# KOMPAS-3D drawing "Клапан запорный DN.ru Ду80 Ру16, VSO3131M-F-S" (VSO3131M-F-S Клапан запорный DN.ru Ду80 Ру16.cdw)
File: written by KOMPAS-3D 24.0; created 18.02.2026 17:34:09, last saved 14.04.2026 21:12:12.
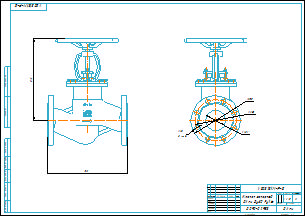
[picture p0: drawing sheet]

Document properties: Автор: R2D2; Форматы листов документа: A2; Полное имя файла: VSO3131M-F-S Клапан запорный DN.ru Ду80 Ру16.m3d; Масса: 20.25; Наименование: Клапан запорный DN.ru Ду80 Ру16; Количество листов документа: 1; Примечание: D090-02953

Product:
- Part/product: Клапан запорный DN.ru Ду80 Ру16  | designation VSO3131M-F-S
    Масса: 20.25
    Раздел спецификации: Прочие изделия
    Примечание: D090-02953

Views: Вид 1, Спереди, Проекционный вид 2
Referenced files in E:\Работа\Зайцев\VSO3131M-F-S Клапан запорный DN.ru Ду15-100 Ру40\DN50\: VSO3131M-F-S Клапан запорный DN.ru Ду50 Ру40.m3d
Referenced files in E:\Работа\Зайцев\VSO3131M-F-S Клапан запорный DN.ru Ду15-100 Ру16\DN80\: VSO3131M-F-S Клапан запорный DN.ru Ду80 Ру16.m3d
Referenced files in E:\Работа\Зайцев\Для компаса\: чертеж DN.ru А3.cdt
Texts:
  Линейный размер
  VSO3131M-F-S
  чертеж DN.ru А3.cdt
  Клапан запорный
  DN.ru Ду80 Ру16
  Клапан запорный DN.ru Ду80 Ру16
  VSO3131M-F-S Клапан запорный DN.ru Ду80 Ру16
Dimensions and other numbers on the sheet: 0; 3; 2; 4; 310; 320; 195; 160; 80; 18; 8 отв.; 1:2; 1; 20,25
